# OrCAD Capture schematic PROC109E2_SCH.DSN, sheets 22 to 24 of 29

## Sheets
22 22. XDS110_DEBUGGER: size C; title: XDS110 DEBUGGER
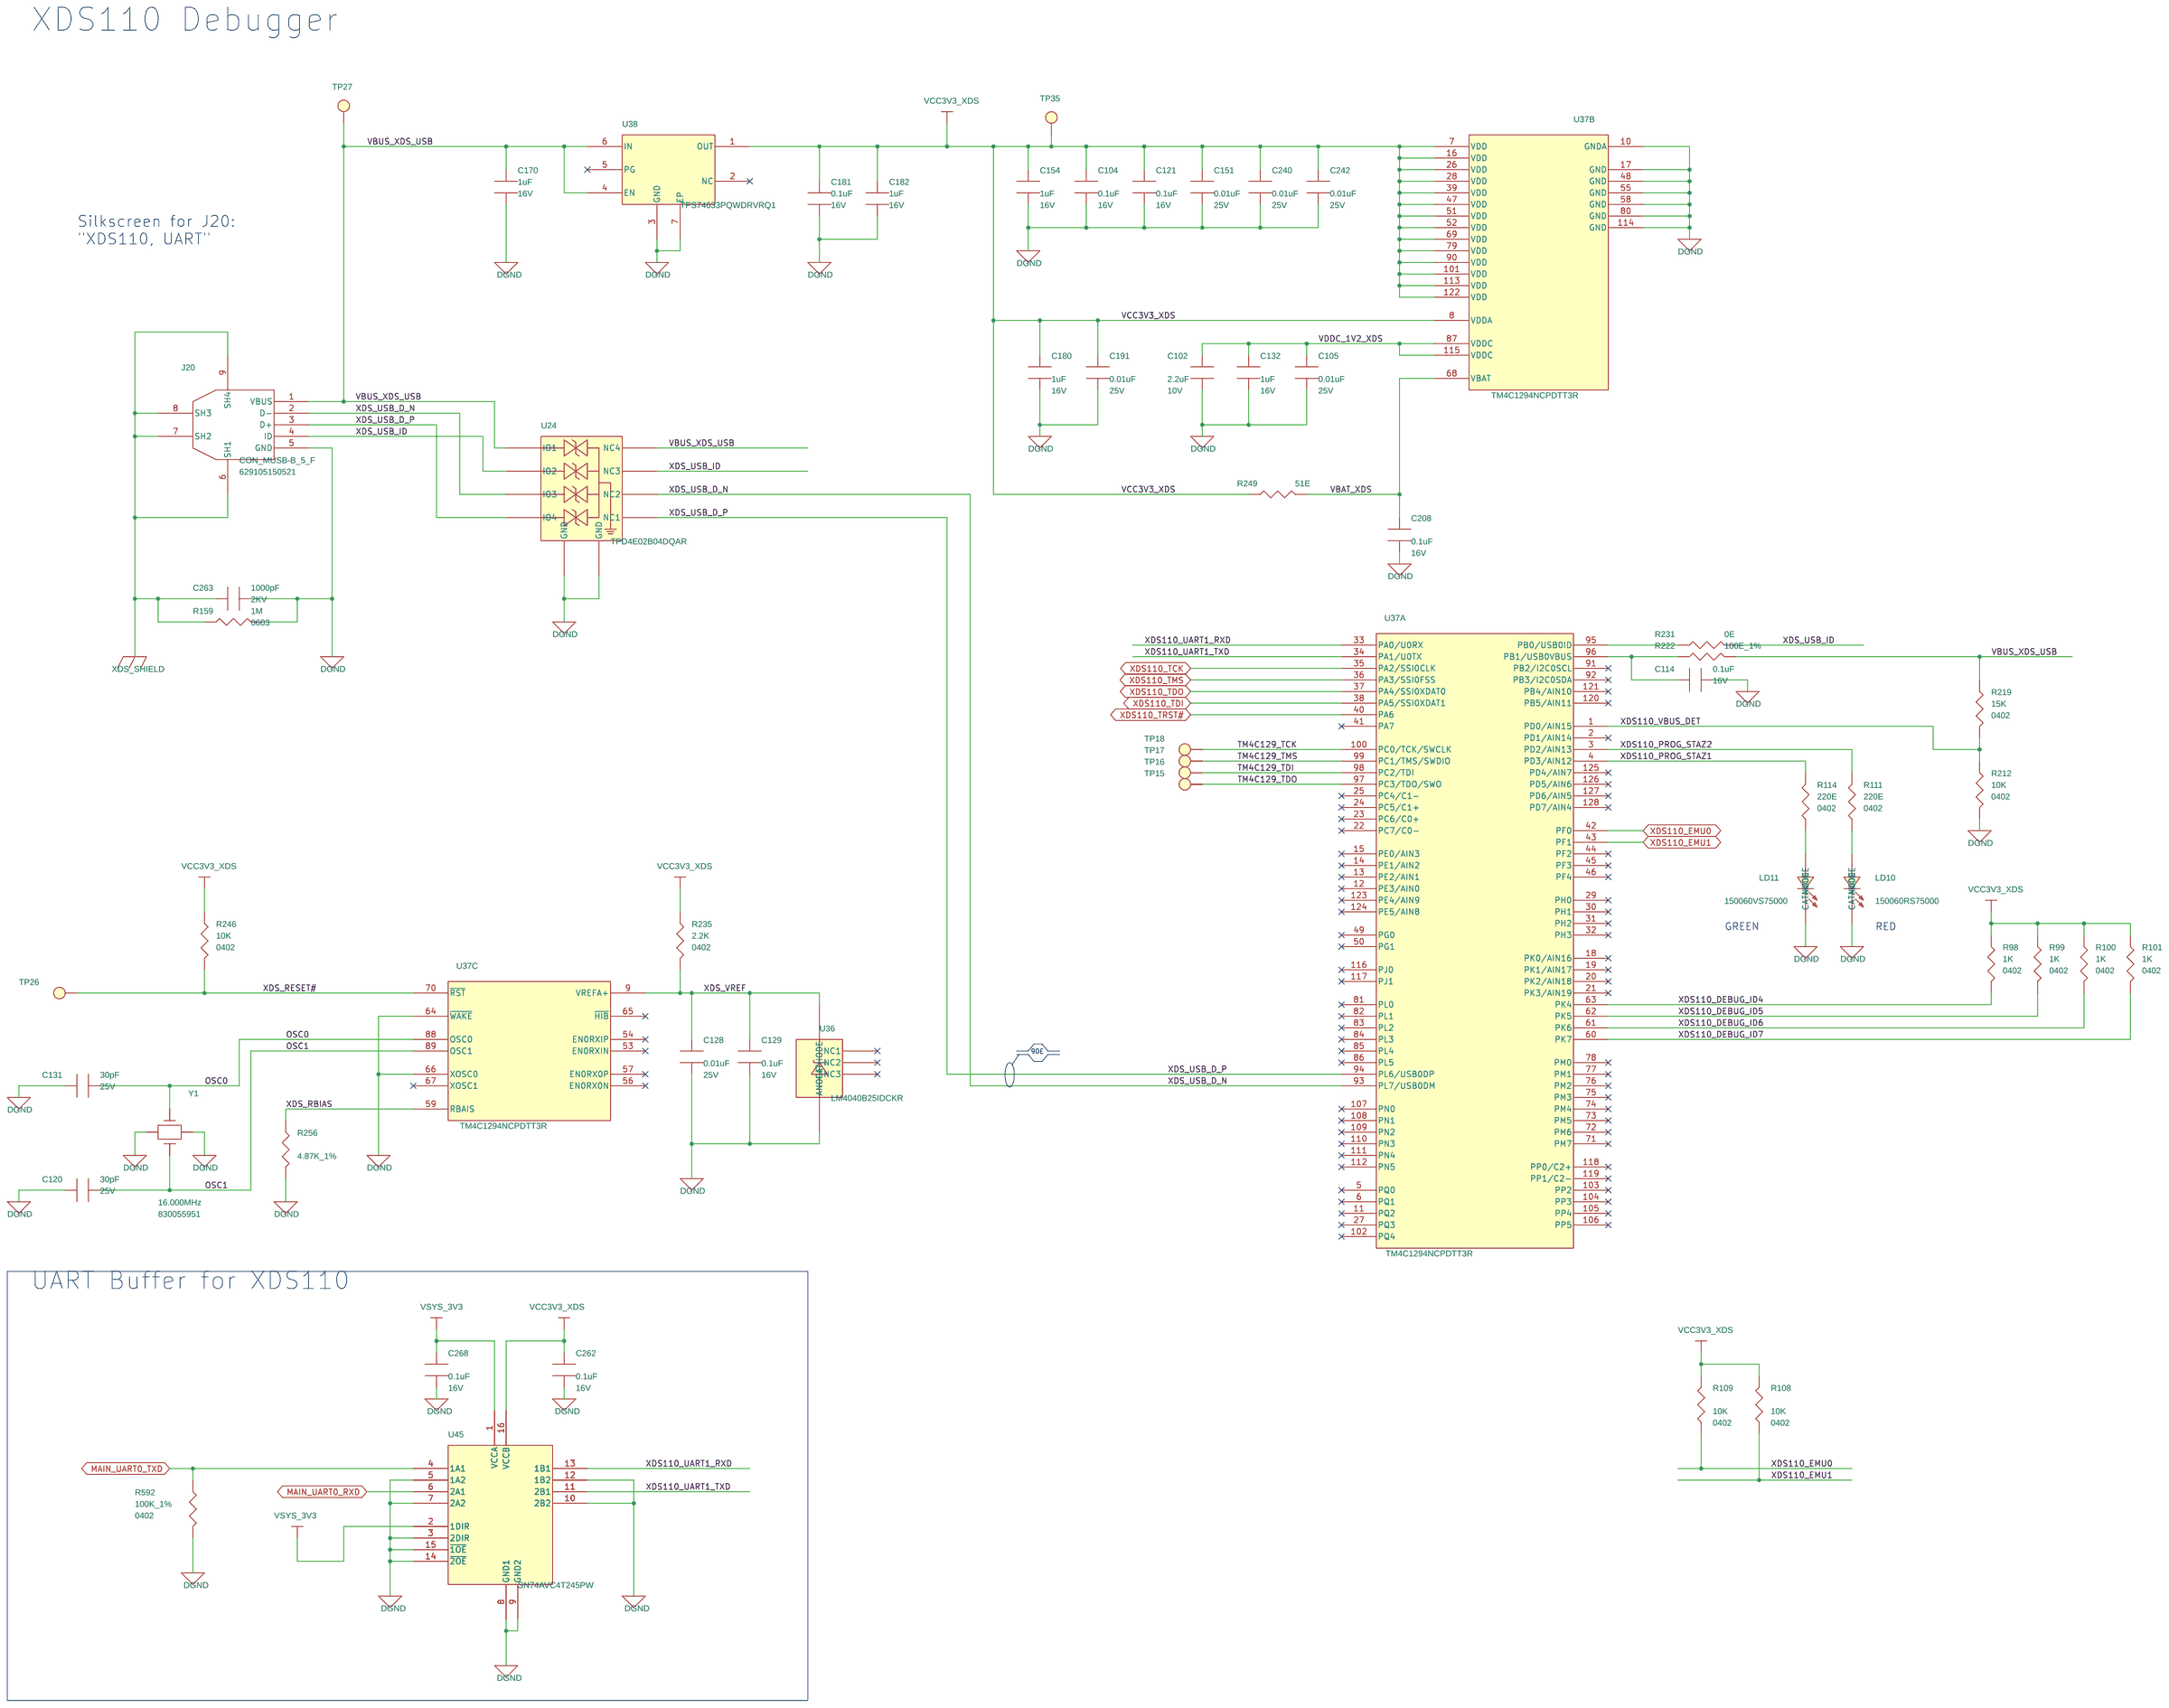
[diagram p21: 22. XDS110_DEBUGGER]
23 23. INDUSTRIAL_COMM_LEDs: size C; title: INDUSTRIAL COMMUNICATION LEDs
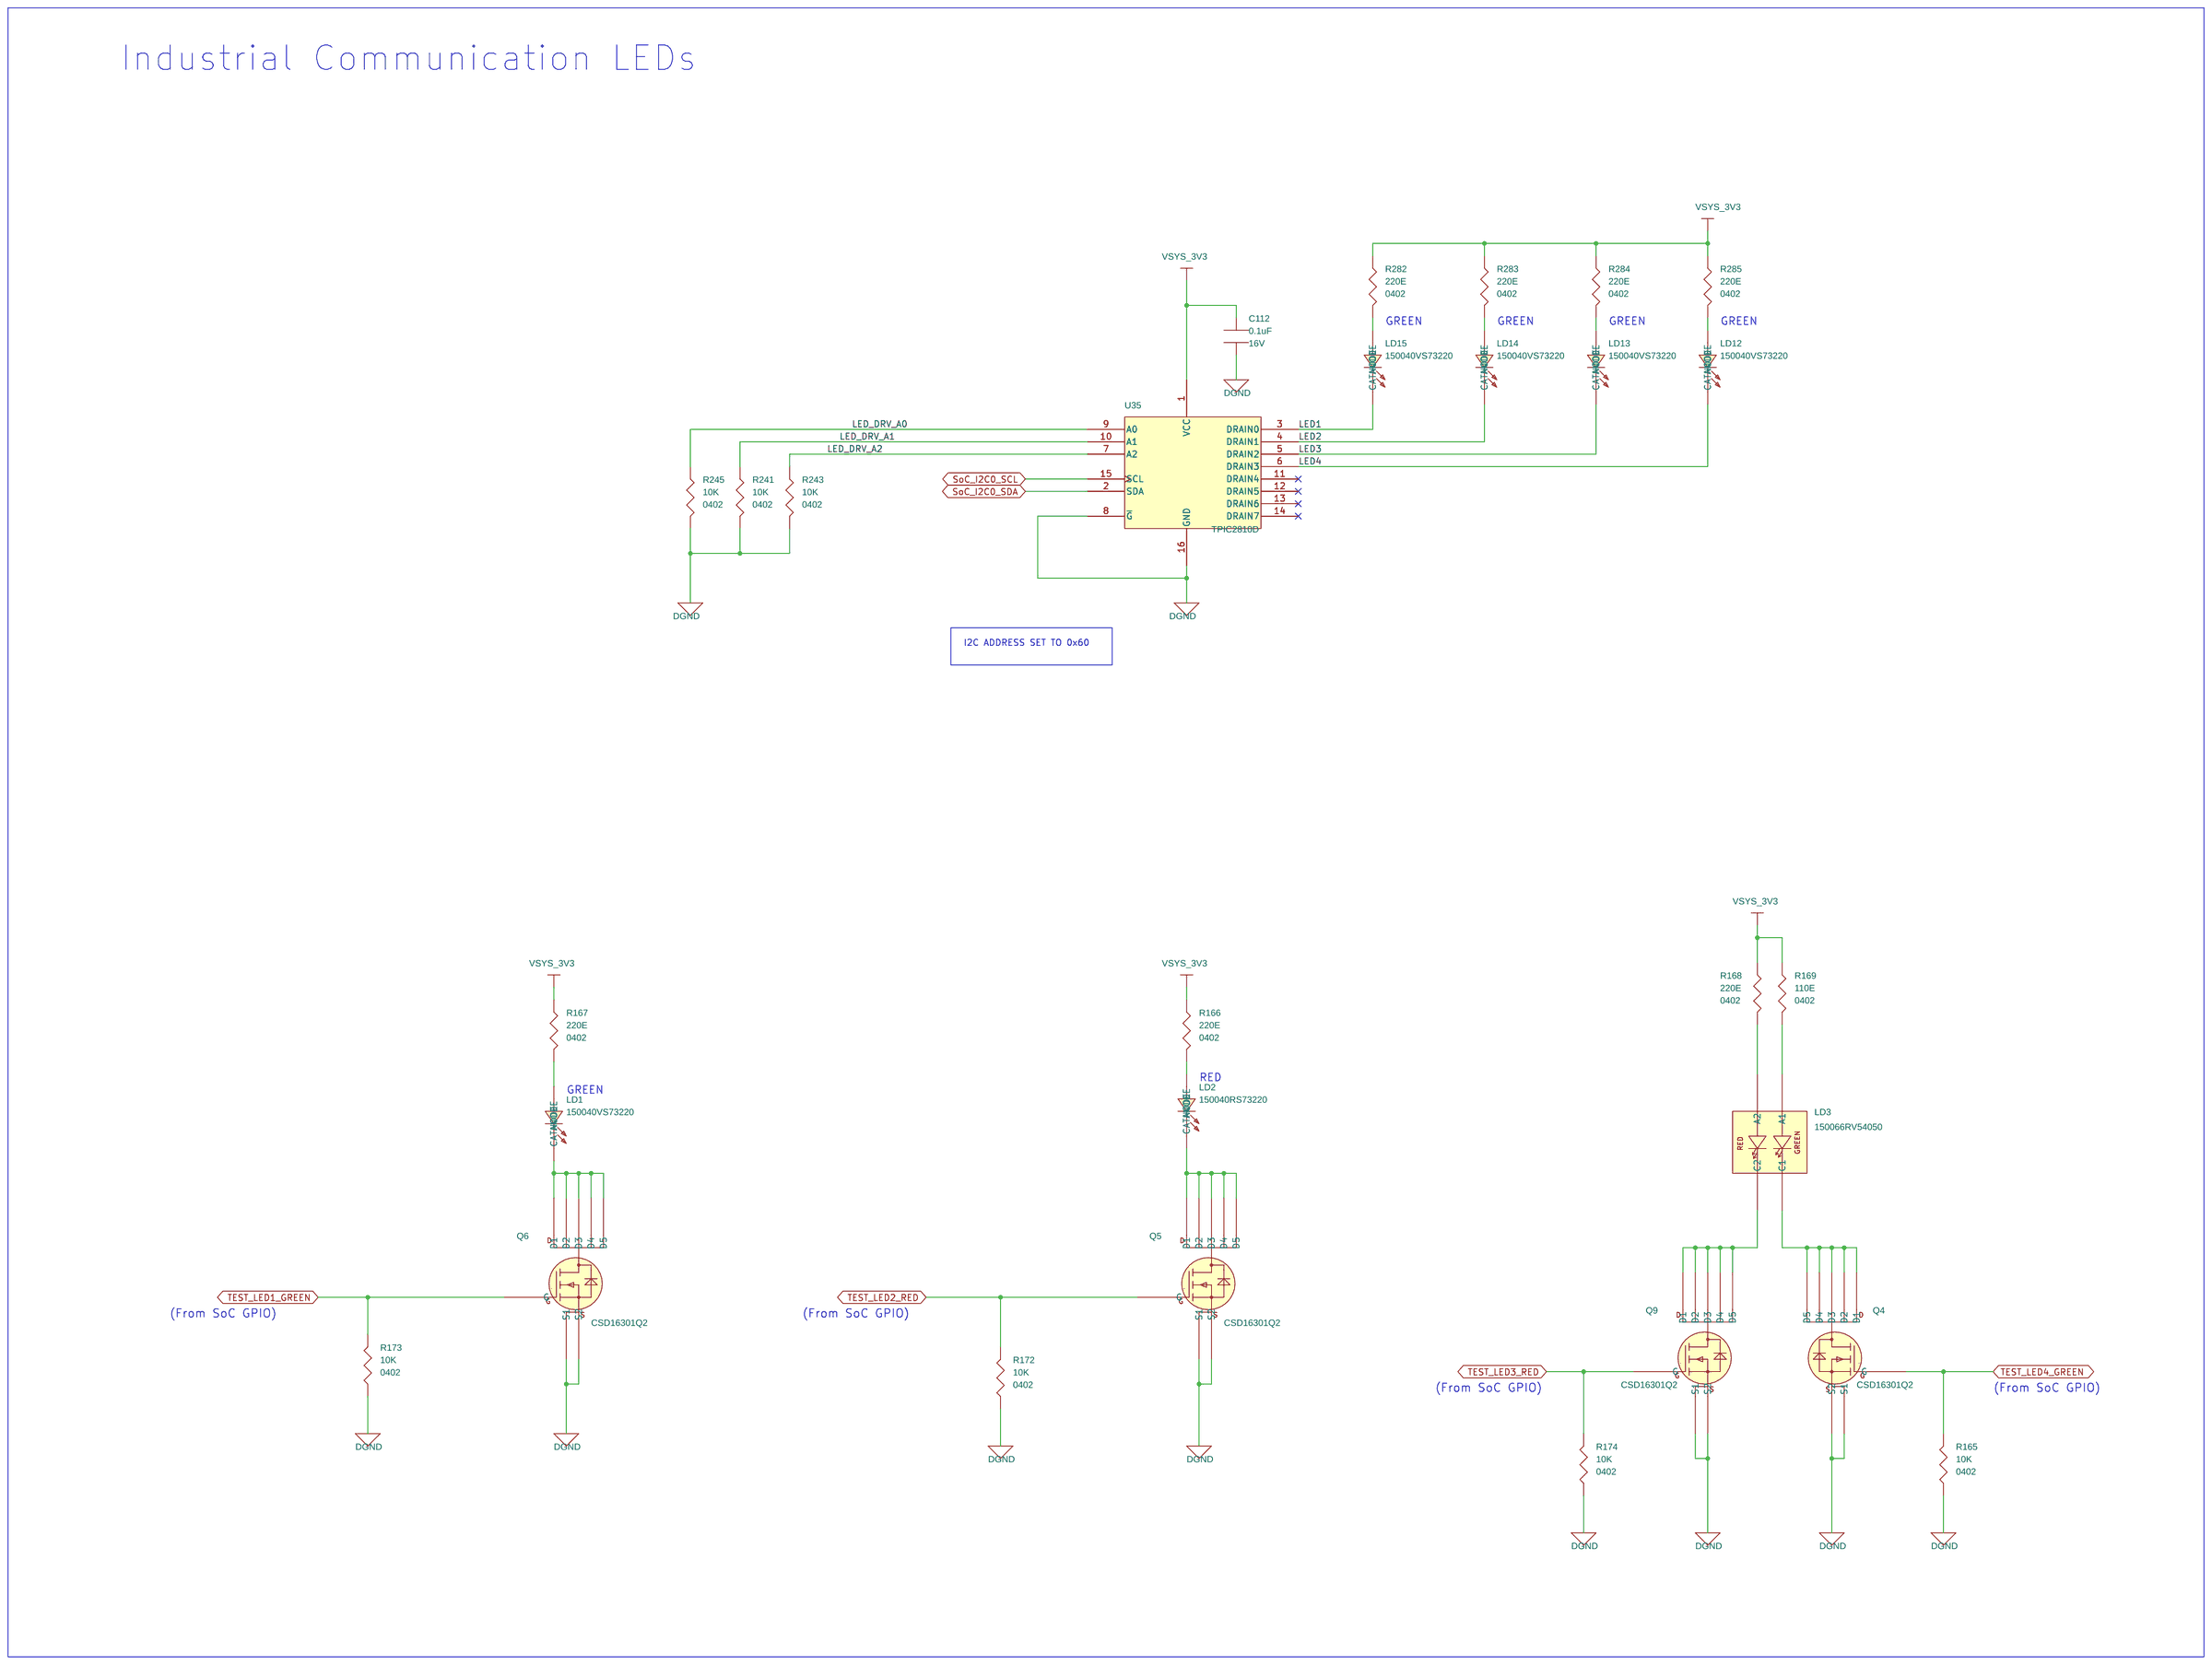
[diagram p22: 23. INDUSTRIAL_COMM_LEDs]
24 24. SOC_DIGITAL_POWER_DECAPs: size C; title: SoC Digital POWER & DECAPs
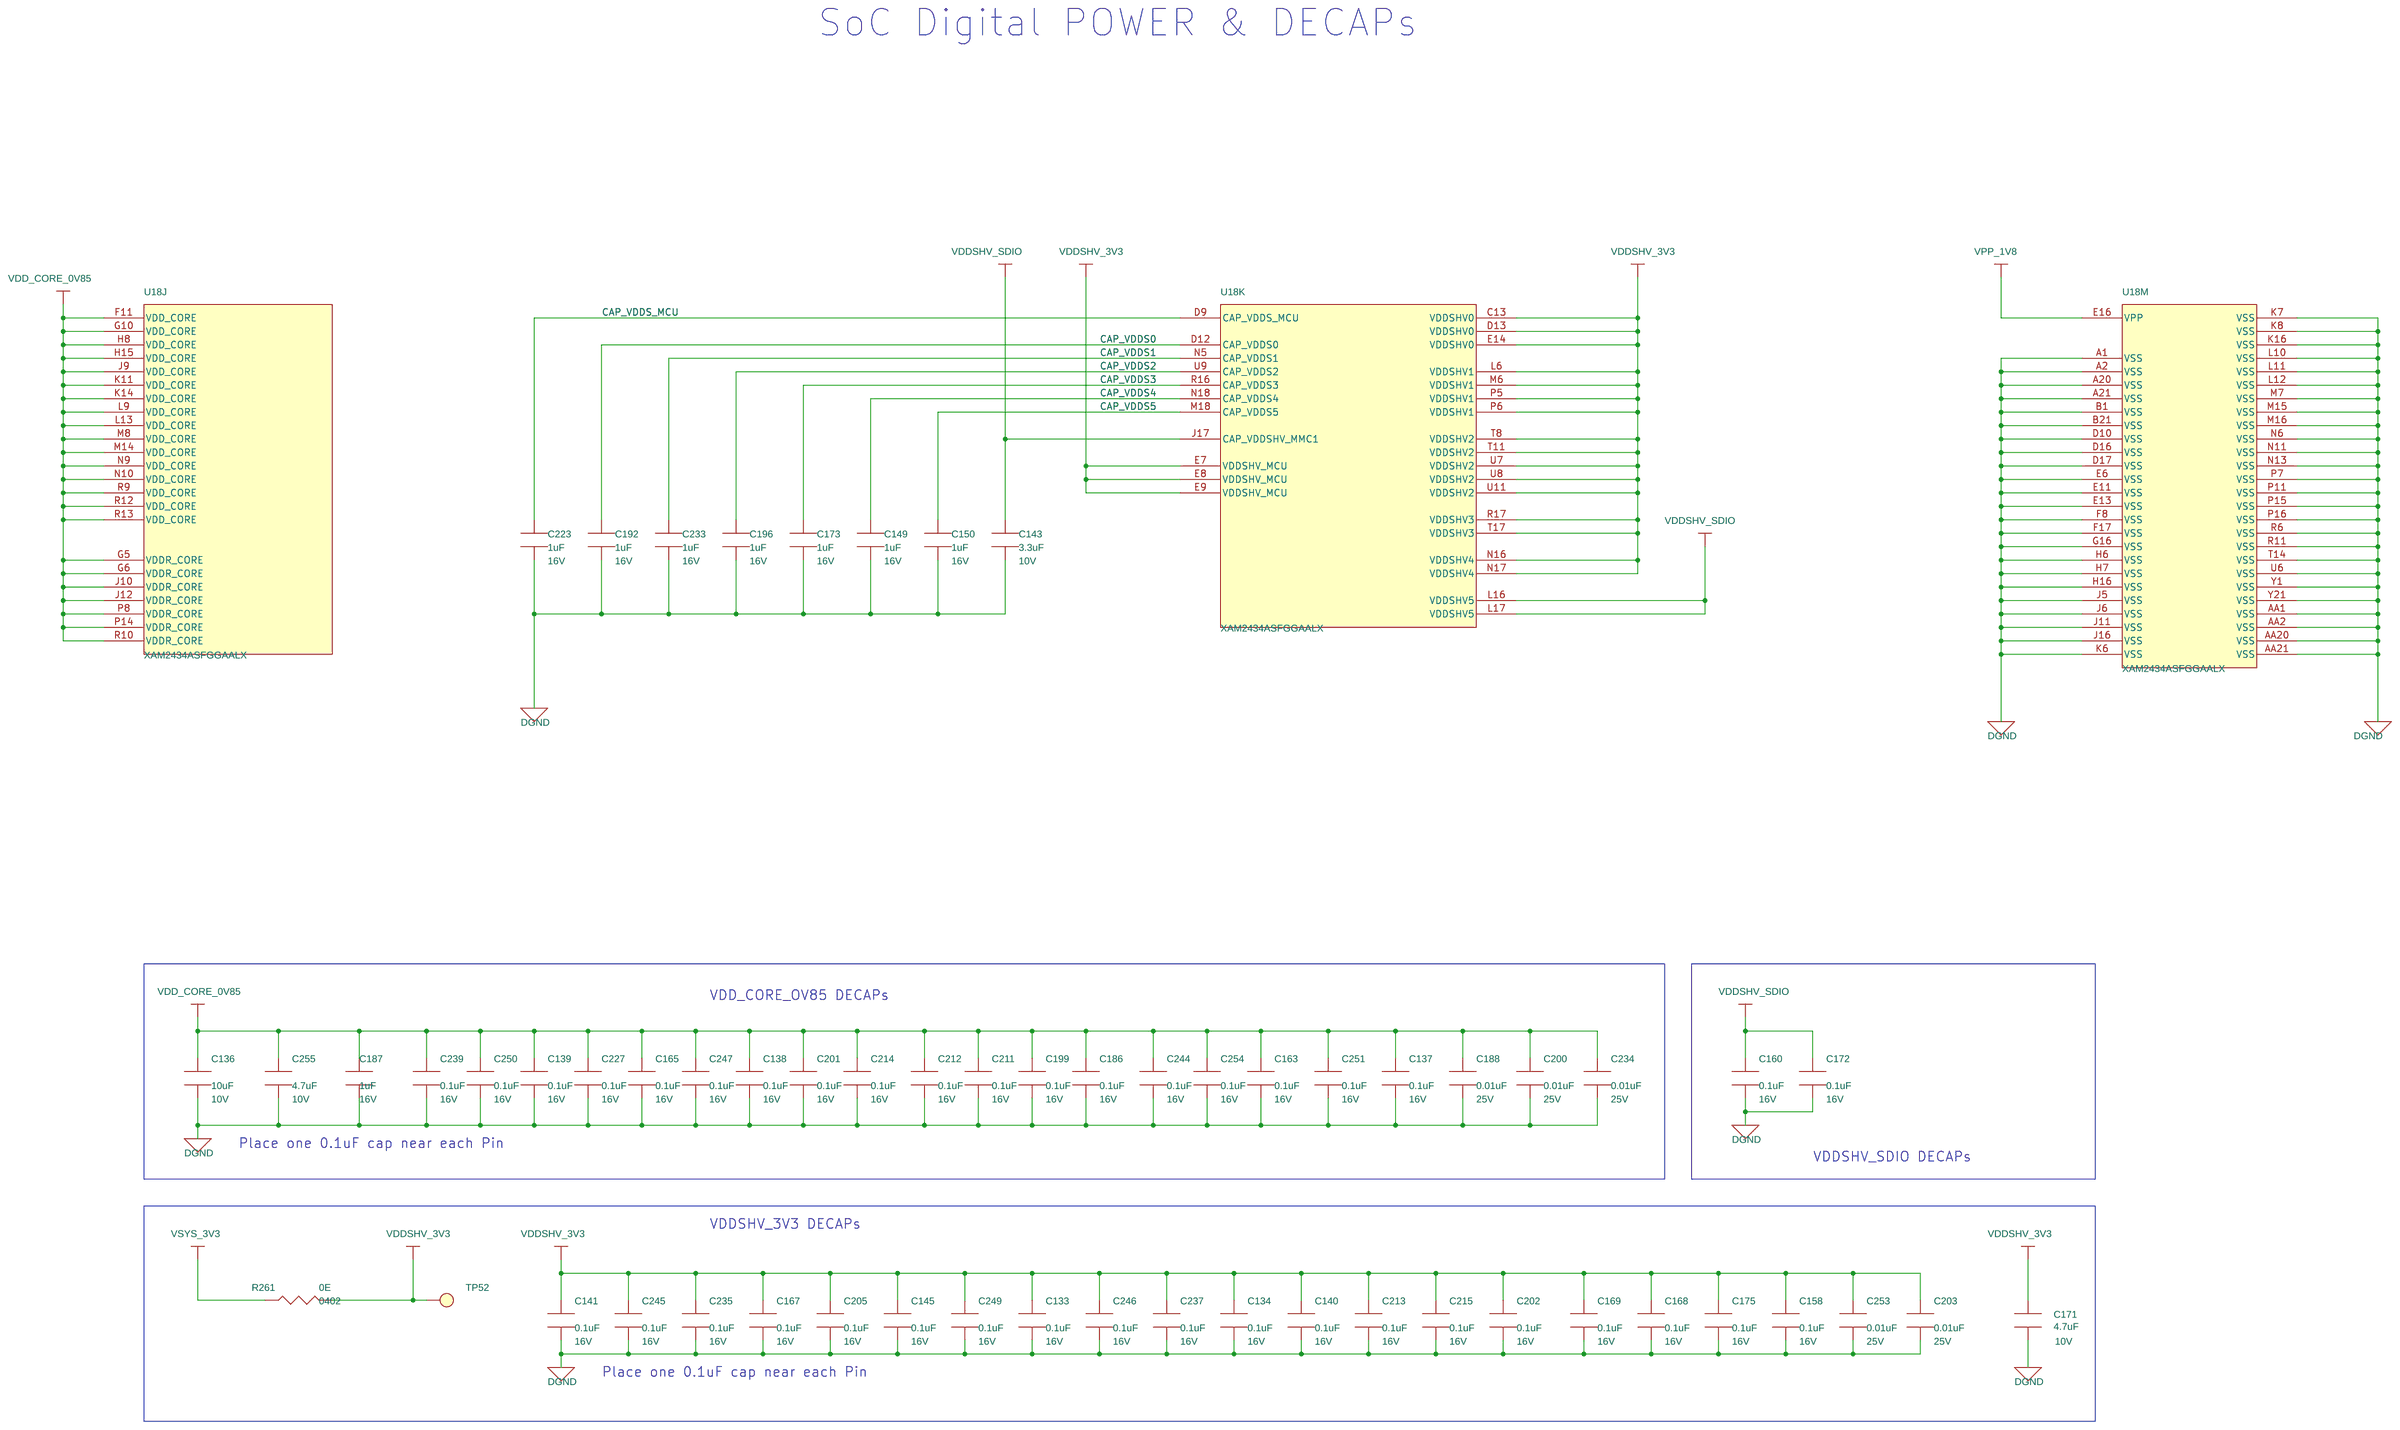
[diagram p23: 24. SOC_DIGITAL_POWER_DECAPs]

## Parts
sheet 15. SOC_QSPI_BOARD_ID_EEPROM
U18  XAM2434ASFGGAALX  [BGA293_19-68_440X440_1]  (sections A,B,C,D,E,F,G,H,I,J,K,L,M)
sheet 22. XDS110_DEBUGGER
C102  2.2uF  [CAP0402_0-75]
C104  0.1uF  [CAP0201_0-5]
C105  0.01uF  [CAP0201_0-5]
C114  0.1uF  [CAP0201_0-5]
C120  30pF  [CAP0201_0-5]
C121  0.1uF  [CAP0201_0-5]
C128  0.01uF  [CAP0201_0-5]
C129  0.1uF  [CAP0201_0-5]
C131  30pF  [CAP0201_0-5]
C132  1uF  [CAP0201_0-5]
C151  0.01uF  [CAP0201_0-5]
C154  1uF  [CAP0201_0-5]
C170  1uF  [CAP0201_0-5]
C180  1uF  [CAP0201_0-5]
C181  0.1uF  [CAP0201_0-5]
C182  1uF  [CAP0201_0-5]
C191  0.01uF  [CAP0201_0-5]
C208  0.1uF  [CAP0201_0-5]
C240  0.01uF  [CAP0201_0-5]
C242  0.01uF  [CAP0201_0-5]
C262  0.1uF  [CAP0201_0-5]
C263  1000pF  [CAP1210_1-5]
C268  0.1uF  [CAP0201_0-5]
J20  CON_MUSB-B_5_F  [CON_MUSBB5_629105150521_S_R_S_2-7]
LD10  150060RS75000  [LED_150060SS75000_70X40_SMD_0-8]
LD11  150060VS75000  [LED_150060SS75000_70X40_SMD_0-8]
R98  1K  [RES0402_0-5]
R99  1K  [RES0402_0-5]
R100  1K  [RES0402_0-5]
R101  1K  [RES0402_0-5]
R108  10K  [RES0402_0-5]
R109  10K  [RES0402_0-5]
R111  220E  [RES0402_0-5]
R114  220E  [RES0402_0-5]
R159  1M  [RES0603_0-75]
R212  10K  [RES0402_0-5]
R219  15K  [RES0402_0-5]
R222  100E_1%  [RES0402_0-5]
R231  0E  [RES0402_0-5]
R235  2.2K  [RES0402_0-5]
R246  10K  [RES0402_0-5]
R249  51E  [RES0402_0-5]
R256  4.87K_1%  [RES0402_0-5]
R592  100K_1%  [RES0402_0-5]
TP15  TP20_SMD  [TP20_SMD]
TP16  TP20_SMD  [TP20_SMD]
TP17  TP20_SMD  [TP20_SMD]
TP18  TP20_SMD  [TP20_SMD]
TP26  TP20_SMD  [TP20_SMD]
TP27  TP40_SMD  [TP40_SMD]
TP35  TP40_SMD  [TP40_SMD]
U24  TPD4E02B04DQAR  [USON10_TPD4E05U_40X100_0-6]
U36  LM4040B25IDCKR  [SC70-5_1-1]
U37  TM4C1294NCPDTT3R  [TQFP128_15-74_550X550_1-2]  (sections A,B,C)
U38  TPS74633PQWDRVRQ1  [SON6_25-59_85X85_0-8]
U45  SN74AVC4T245PW  [TSSOP16_25-59_205X180]
Y1  16.000MHz  [XTAL4_LFXTAL055474_130X110_SMD_0-8]
sheet 23. INDUSTRIAL_COMM_LEDs
C112  0.1uF  [CAP0201_0-5]
LD1  150040VS73220  [LED_150040GS73220_40X20_SMD_0-4]
LD2  150040RS73220  [LED_150040GS73220_40X20_SMD_0-4]
LD3  150066RV54050  [LED4_150066RV54050_70X60_SMD_0-7]
LD12  150040VS73220  [LED_150040GS73220_40X20_SMD_0-4]
LD13  150040VS73220  [LED_150040GS73220_40X20_SMD_0-4]
LD14  150040VS73220  [LED_150040GS73220_40X20_SMD_0-4]
LD15  150040VS73220  [LED_150040GS73220_40X20_SMD_0-4]
Q4  CSD16301Q2  [WSON6_CSD13202Q2_80X80_0-8]
Q5  CSD16301Q2  [WSON6_CSD13202Q2_80X80_0-8]
Q6  CSD16301Q2  [WSON6_CSD13202Q2_80X80_0-8]
Q9  CSD16301Q2  [WSON6_CSD13202Q2_80X80_0-8]
R165  10K  [RES0402_0-5]
R166  220E  [RES0402_0-5]
R167  220E  [RES0402_0-5]
R168  220E  [RES0402_0-5]
R169  110E  [RES0402_0-5]
R172  10K  [RES0402_0-5]
R173  10K  [RES0402_0-5]
R174  10K  [RES0402_0-5]
R241  10K  [RES0402_0-5]
R243  10K  [RES0402_0-5]
R245  10K  [RES0402_0-5]
R282  220E  [RES0402_0-5]
R283  220E  [RES0402_0-5]
R284  220E  [RES0402_0-5]
R285  220E  [RES0402_0-5]
U35  TPIC2810D  [SOIC16_1-8]
sheet 24. SOC_DIGITAL_POWER_DECAPs
C133  0.1uF  [CAP0201_0-5]
C134  0.1uF  [CAP0201_0-5]
C136  10uF  [CAP0402_0-75]
C137  0.1uF  [CAP0201_0-5]
C138  0.1uF  [CAP0201_0-5]
C139  0.1uF  [CAP0201_0-5]
C140  0.1uF  [CAP0201_0-5]
C141  0.1uF  [CAP0201_0-5]
C143  3.3uF  [CAP0603_1]
C145  0.1uF  [CAP0201_0-5]
C149  1uF  [CAP0201_0-5]
C150  1uF  [CAP0201_0-5]
C158  0.1uF  [CAP0201_0-5]
C160  0.1uF  [CAP0201_0-5]
C163  0.1uF  [CAP0201_0-5]
C165  0.1uF  [CAP0201_0-5]
C167  0.1uF  [CAP0201_0-5]
C168  0.1uF  [CAP0201_0-5]
C169  0.1uF  [CAP0201_0-5]
C171  4.7uF  [CAP0402_0-75]
C172  0.1uF  [CAP0201_0-5]
C173  1uF  [CAP0201_0-5]
C175  0.1uF  [CAP0201_0-5]
C186  0.1uF  [CAP0201_0-5]
C187  1uF  [CAP0201_0-5]
C188  0.01uF  [CAP0201_0-5]
C192  1uF  [CAP0201_0-5]
C196  1uF  [CAP0201_0-5]
C199  0.1uF  [CAP0201_0-5]
C200  0.01uF  [CAP0201_0-5]
C201  0.1uF  [CAP0201_0-5]
C202  0.1uF  [CAP0201_0-5]
C203  0.01uF  [CAP0201_0-5]
C205  0.1uF  [CAP0201_0-5]
C211  0.1uF  [CAP0201_0-5]
C212  0.1uF  [CAP0201_0-5]
C213  0.1uF  [CAP0201_0-5]
C214  0.1uF  [CAP0201_0-5]
C215  0.1uF  [CAP0201_0-5]
C223  1uF  [CAP0201_0-5]
C227  0.1uF  [CAP0201_0-5]
C233  1uF  [CAP0201_0-5]
C234  0.01uF  [CAP0201_0-5]
C235  0.1uF  [CAP0201_0-5]
C237  0.1uF  [CAP0201_0-5]
C239  0.1uF  [CAP0201_0-5]
C244  0.1uF  [CAP0201_0-5]
C245  0.1uF  [CAP0201_0-5]
C246  0.1uF  [CAP0201_0-5]
C247  0.1uF  [CAP0201_0-5]
C249  0.1uF  [CAP0201_0-5]
C250  0.1uF  [CAP0201_0-5]
C251  0.1uF  [CAP0201_0-5]
C253  0.01uF  [CAP0201_0-5]
C254  0.1uF  [CAP0201_0-5]
C255  4.7uF  [CAP0402_0-75]
R261  0E  [RES0402_0-5]
TP52  TP20_SMD  [TP20_SMD]

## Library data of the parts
U18 = AM243X_SOC_LP_EVM_BGA293: IC AM243x SoC_LP_EVM MICROPROCESSOR BGA293; Chkd/date: MANIRAJA/131120; Crtd /date: ALVY/121120; Custom_Duty: 15%; Customs_HS_Code: 85423100; Distributor_name: NA; Distributor_part_number: NA; Footprint Path: Y:\MIS_DATABASE\Library\ALTIUM_TOOL\PCB_FOOTPRINTS\Altium_Footprint_Lib.PcbLib; Height: 1.00MM; Library Path: Y:\MIS_DATABASE\Library\ALTIUM_TOOL\SCHEMATICS_PARTS\MS_MICROPROCESSOR_Library.schlib; Library Ref: AM243x SoC_LP_EVM_BGA293; Mfr_name: TEXAS INSTRUMENTS; Mistral Part No: 141220110003; Package: BGA293; Part_type: ICS\DIGITAL\MICROPROCESSOR; Project: TI_AM243x LP EVM; RoHS: NA; Temperature: NA; Tolerance: NA; Voltage: NA; Wattage: NA; Weight: NA; Datasheet: Y:\MIS_DATABASE\DATASHEETS\ICS\DIGITAL\MICROCONTROLLER\AM243x SoC-FP.PDF
C102 = CAP: CAP CERAMIC 2.2uF 10V 20% X5R 0402; Chkd/date: MANIRAJA/170820; Crtd /date: ALVY/170820; Custom_Duty: 15%; Customs_HS_Code: 85322990; Distributor_name: DIGIKEY; Distributor_part_number: 732-7490-1-ND; Footprint Path: Y:\MIS_DATABASE\Library\ALTIUM_TOOL\PCB_FOOTPRINTS\Altium_Footprint_Lib.PcbLib; Height: 0.55MM; Library Path: Y:\MIS_DATABASE\Library\ALTIUM_TOOL\SCHEMATICS_PARTS\MS_DISCRETE_Library.schlib; Mfr_name: WURTH ELECTRONICS; Mfr_part_number: 885012105013; Mistral Part No: 120019040036-R; Package: 0402; Part_type: CAPACITORS\CERAMIC; Project: AM64x_EVM_BRD; RoHS: RoHS; Temperature: -55°C+85°C; Tolerance: 20%; Voltage: 10V; Wattage: NA; Weight: 0.65mg; Datasheet: Y:\MIS_DATABASE\DATASHEETS\CAPACITORS\885012105013.PDF
C104 C114 C121 C129 C133 C134 C137-C141 C145 C158 C160 C163 C165 C167-C169 C172 C175 C181 C186 C199 C201 C202 C205 C208 C211-C215 C227 C235 C237 C239 C244-C247 C249-C251 C254 C262 C268 = CAP: CAP CERAMIC 0.1uF 16V 10% X5R 0201; Chkd/date: MANIRAJA/230118; Crtd /date: MANIRAJA/230118; Custom_Duty: 15%; Customs_HS_Code: 85322990; Distributor_name: DIGIKEY; Distributor_part_number: 490-14305-1-ND; Footprint Path: Y:\MIS_DATABASE\Library\ALTIUM_TOOL\PCB_FOOTPRINTS\Altium_Footprint_Lib.PcbLib; Height: 0.33MM; Library Path: Y:\MIS_DATABASE\Library\ALTIUM_TOOL\SCHEMATICS_PARTS\MS_DISCRETE_Library.schlib; Mfr_name: MURATA; Mfr_part_number: GRM033R61C104KE14D; Mistral Part No: 120009030072-R; Package: 0201; Part_type: CAPACITORS\CERAMIC; Project: TI_MAXIE_CPB; RoHS: RoHS; Temperature: -55°C+85°C; Tolerance: 10%; Voltage: 16V; Wattage: NA; Weight: 0.33mg; Datasheet: Y:\MIS_DATABASE\DATASHEETS\CAPACITORS\GRM033R61C104KE14.PDF
C105 C128 C151 C188 C191 C200 C203 C234 C240 C242 C253 = CAP: CAP CERAMIC 0.01uF 25V 10% X7R 0201; Chkd/date: MANIRAJA/080519; Crtd /date: ALVY/080519; Custom_Duty: 15%; Customs_HS_Code: 85322990; Distributor_name: DIGIKEY; Distributor_part_number: 490-14454-1-ND; Footprint Path: Y:\MIS_DATABASE\Library\ALTIUM_TOOL\PCB_FOOTPRINTS\Altium_Footprint_Lib.PcbLib; Height: 0.33MM; Library Path: Y:\MIS_DATABASE\Library\ALTIUM_TOOL\SCHEMATICS_PARTS\MS_DISCRETE_Library.schlib; Mfr_name: MURATA; Mfr_part_number: GRM033R71E103KE14D; Mistral Part No: 120019050002-R; Package: 0201; Part_type: CAPACITORS\CERAMIC; Project: BRUKER_SD820_COMMONDO; RoHS: RoHS; Temperature: -55°C+125°C; Tolerance: 10%; Voltage: 25V; Wattage: NA; Weight: 0.33mg; Datasheet: Y:\MIS_DATABASE\DATASHEETS\CAPACITORS\GRM033R71E103KE14.PDF
C120 C131 = CAP: CAP CERAMIC 30pF 25V 5% C0G(NP0) 0201; Chkd/date: ALVY/050221; Crtd /date: MANIRAJA/050221; Custom_Duty: 15%; Customs_HS_Code: 85322990; Distributor_name: DIGIKEY; Distributor_part_number: 490-12677-1-ND; Footprint Path: Y:\MIS_DATABASE\Library\ALTIUM_TOOL\PCB_FOOTPRINTS\Altium_Footprint_Lib.PcbLib; Height: 0.33MM; Library Path: Y:\MIS_DATABASE\Library\ALTIUM_TOOL\SCHEMATICS_PARTS\MS_DISCRETE_Library.schlib; Mfr_name: MURATA; Mfr_part_number: GRM0335C1E300JA01D; Mistral Part No: 120009030363-R; Package: 0201; Part_type: CAPACITORS\CERAMIC; Project: TI_AM243x LP EVM; RoHS: RoHS; Temperature: -55°C+125°C; Tolerance: 5%; Voltage: 25V; Wattage: NA; Weight: 0.33mg; Datasheet: Y:\MIS_DATABASE\DATASHEETS\CAPACITORS\GRM0335C1E300JA01.PDF
C132 C149 C150 C154 C170 C173 C180 C182 C187 C192 C196 C223 C233 = CAP: CAP CERAMIC 1uF 16V 20% X5R 0201; Chkd/date: MANIRAJA/300520; Crtd /date: ALVY/260520; Custom_Duty: 15%; Customs_HS_Code: 85322990; Distributor_name: DIGIKEY; Distributor_part_number: 490-18654-1-ND; Footprint Path: Y:\MIS_DATABASE\Library\ALTIUM_TOOL\PCB_FOOTPRINTS\Altium_Footprint_Lib.PcbLib; Height: 0.39MM; Library Path: Y:\MIS_DATABASE\Library\ALTIUM_TOOL\SCHEMATICS_PARTS\MS_DISCRETE_Library.schlib; Mfr_name: MURATA; Mfr_part_number: GRM033R61C105ME15D; Mistral Part No: 120018090038-R; Package: 0201; Part_type: CAPACITORS\CERAMIC; Project: QCS610_NANOSOM; RoHS: RoHS; Temperature: -55°C+85°C; Tolerance: 20%; Voltage: 16V; Wattage: NA; Weight: 0.33mg; Datasheet: Y:\MIS_DATABASE\DATASHEETS\CAPACITORS\GRM033R61C105ME15.PDF
C263 = CAP: CAP CERAMIC 1000pF 2KV 10% X7R 1210; Chkd/date: ALVY/071220; Crtd /date: MANIRAJA/071220; Custom_Duty: 15%; Customs_HS_Code: 85322990; Distributor_name: DIGIKEY; Distributor_part_number: 732-12130-1-ND; Footprint Path: Y:\MIS_DATABASE\Library\ALTIUM_TOOL\PCB_FOOTPRINTS\Altium_Footprint_Lib.PcbLib; Height: 1.35MM; Library Path: Y:\MIS_DATABASE\Library\ALTIUM_TOOL\SCHEMATICS_PARTS\MS_DISCRETE_Library.schlib; Mfr_name: WURTH ELEKTRONIK; Mfr_part_number: 885342209009; Mistral Part No: 120020120008-R; Package: 1210; Part_type: CAPACITORS\CERAMIC; Project: TI_AM243x LP EVM; RoHS: RoHS; Temperature: -55°C+125°C; Tolerance: 10%; Voltage: 2KV; Wattage: NA; Weight: 19.234mg; Datasheet: Y:\MIS_DATABASE\DATASHEETS\CAPACITORS\885342209009.PDF
J20 = CON_USB_MINI-B: CON MICRO USB TYPE B 5POS FEMALE RT SMD; Chkd/date: MANIRAJA/150519; Crtd /date: ALVY/150519; Custom_Duty: 24%; Customs_HS_Code: 85369090; Distributor_name: DIGIKEY; Distributor_part_number: 732-5960-1-ND; Footprint Path: Y:\MIS_DATABASE\Library\ALTIUM_TOOL\PCB_FOOTPRINTS\Altium_Footprint_Lib.PcbLib; Height: 2.66MM; Library Path: Y:\MIS_DATABASE\Library\ALTIUM_TOOL\SCHEMATICS_PARTS\MS_CONNECTOR_Library.schlib; Mfr_name: WURTH ELECTRONICS; Mfr_part_number: 629105150521; Mistral Part No: 150019050015-R; Package: SMD; Part_type: CONNECTOR\USB; Project: NEXTNAV_ALT-STATION_ATE_BRD; RoHS: RoHS; Temperature: -40°C+85°C; Tolerance: NA; Voltage: NA; Wattage: NA; Weight: 360mg; Datasheet: Y:\MIS_DATABASE\DATASHEETS\CONNECTORS\629105150521.PDF
LD10 = DIODE_LED: DIODE LED RED SMD; Chkd/date: MANIRAJA/131120; Crtd /date: ALVY/121120; Custom_Duty: 24%; Customs_HS_Code: 85439000; Distributor_name: DIGIKEY; Distributor_part_number: 732-4978-1-ND; Footprint Path: Y:\MIS_DATABASE\Library\ALTIUM_TOOL\PCB_FOOTPRINTS\Altium_Footprint_Lib.PcbLib; Height: 0.80MM; Library Path: Y:\MIS_DATABASE\Library\ALTIUM_TOOL\SCHEMATICS_PARTS\MS_OPTO_Library.schlib; Mfr_name: WURTH ELECTRONICS; Mistral Part No: 130020110037-R; Package: SMD; Part_type: OPTO\LED; Project: TI_AM243x LP EVM; RoHS: RoHS; Temperature: -40°C+85°C; Tolerance: NA; Voltage: NA; Wattage: NA; Weight: 23mg; Datasheet: Y:\MIS_DATABASE\DATASHEETS\DISCRETES\LEDS\150060RS75000.PDF
LD11 = DIODE_LED: DIODE LED BRIGHT GREEN SMD; Chkd/date: MANIRAJA/220720; Crtd /date: ALVY/210720; Custom_Duty: 24%; Customs_HS_Code: 85439000; Distributor_name: DIGIKEY; Distributor_part_number: 732-4980-1-ND; Footprint Path: Y:\MIS_DATABASE\Library\ALTIUM_TOOL\PCB_FOOTPRINTS\Altium_Footprint_Lib.PcbLib; Height: 0.80MM; Library Path: Y:\MIS_DATABASE\Library\ALTIUM_TOOL\SCHEMATICS_PARTS\MS_OPTO_Library.schlib; Mfr_name: WURTH ELECTRONICS; Mistral Part No: 130020070019-R; Package: SMD; Part_type: OPTO\LED; Project: AM64x-IO LINK BRD; RoHS: RoHS; Temperature: -40°C+85°C; Tolerance: NA; Voltage: NA; Wattage: NA; Weight: 25mg; Datasheet: Y:\MIS_DATABASE\DATASHEETS\DISCRETES\LEDS\150060VS75000.PDF
R98-R101 = RESISTOR: RES 1K 1/16W 5% 0402; Chkd/date: VASANTHA/120516; Crtd /date: VASANTHA/120516; Custom_Duty: 15%; Customs_HS_Code: 85332119; Distributor_name: DIGIKEY; Distributor_part_number: 311-1.0KJRCT-ND; Footprint Path: Y:\MIS_DATABASE\Library\ALTIUM_TOOL\PCB_FOOTPRINTS\Altium_Footprint_Lib.PcbLib; Height: 0.40MM; Library Path: Y:\MIS_DATABASE\Library\ALTIUM_TOOL\SCHEMATICS_PARTS\MS_DISCRETE_Library.schlib; Mfr_name: YAGEO AMERICA; Mfr_part_number: RC0402JR-071KL; Mistral Part No: 110010070006-R; Package: 0402; Part_type: RESISTORS\FIXED; Project: TMDXCSK368; RoHS: RoHS; Temperature: -55°C+155°C; Tolerance: 5%; Voltage: NA; Wattage: 1/16W; Weight: 0.65mg; Datasheet: Y:\MIS_DATABASE\DATASHEETS\RESISTORS\RCXXXXL-SER_MAR18.PDF
R108 R109 R165 R172-R174 R212 R241 R243 R245 R246 = RESISTOR: RES 10K 1/16W 5% 0402; Chkd/date: VASANTHA/061216; Crtd /date: MAZHAR/230805; Custom_Duty: 15%; Customs_HS_Code: 85332119; Distributor_name: DIGIKEY; Distributor_part_number: 311-10KJRCT-ND; Footprint Path: Y:\MIS_DATABASE\Library\ALTIUM_TOOL\PCB_FOOTPRINTS\Altium_Footprint_Lib.PcbLib; Height: 0.40MM; Library Path: Y:\MIS_DATABASE\Library\ALTIUM_TOOL\SCHEMATICS_PARTS\MS_DISCRETE_Library.schlib; Mfr_name: YAGEO AMERICA; Mfr_part_number: RC0402JR-0710KL; Mistral Part No: 110011060021-R; Package: 0402; Part_type: RESISTORS\FIXED; Project: HSE; RoHS: RoHS; Temperature: -55°C+155°C; Tolerance: 5%; Voltage: NA; Wattage: 1/16W; Weight: 0.65mg; Datasheet: Y:\MIS_DATABASE\DATASHEETS\RESISTORS\RCXXXXL-SER_MAR18.PDF
R111 R114 R166-R168 R282-R285 = RESISTOR: RES 220E 1/16W 5% 0402; Chkd/date: ALVY/091220; Crtd /date: MANIRAJA/091220; Custom_Duty: 15%; Customs_HS_Code: 85332119; Distributor_name: DIGIKEY; Distributor_part_number: 311-220JRCT-ND; Footprint Path: Y:\MIS_DATABASE\Library\ALTIUM_TOOL\PCB_FOOTPRINTS\Altium_Footprint_Lib.PcbLib; Height: 0.40MM; Library Path: Y:\MIS_DATABASE\Library\ALTIUM_TOOL\SCHEMATICS_PARTS\MS_DISCRETE_Library.schlib; Mfr_name: YAGEO AMERICA; Mfr_part_number: RC0402JR-07220RL; Mistral Part No: 110020120013-R; Package: 0402; Part_type: RESISTORS\FIXED; Project: TI_AM243x LP EVM; RoHS: RoHS; Temperature: -55°C+155°C; Tolerance: 5%; Voltage: NA; Wattage: 1/16W; Weight: 0.65mg; Datasheet: Y:\MIS_DATABASE\DATASHEETS\RESISTORS\RCXXXXL-SER_MAR18.PDF
R159 = RESISTOR: RES 1M 1/10W 5% 0603; Chkd/date: ALVY/091220; Crtd /date: MANIRAJA/091220; Custom_Duty: 15%; Customs_HS_Code: 85332119; Distributor_name: DIGIKEY; Distributor_part_number: 311-1.0MGRCT-ND; Footprint Path: Y:\MIS_DATABASE\Library\ALTIUM_TOOL\PCB_FOOTPRINTS\Altium_Footprint_Lib.PcbLib; Height: 0.55MM; Library Path: Y:\MIS_DATABASE\Library\ALTIUM_TOOL\SCHEMATICS_PARTS\MS_DISCRETE_Library.schlib; Mfr_name: YAGEO AMERICA; Mfr_part_number: RC0603JR-071ML; Mistral Part No: 110009030413-R; Package: 0603; Part_type: RESISTORS\FIXED; Project: TI_AM243x LP EVM; RoHS: RoHS; Temperature: -55°C+155°C; Tolerance: 5%; Voltage: NA; Wattage: 1/10W; Weight: 2mg; Datasheet: Y:\MIS_DATABASE\DATASHEETS\RESISTORS\RCXXXXL-SER_MAR18.PDF
R219 = RESISTOR: RES 15K 1/10W 5% 0402; Chkd/date: VASANTHA/061216; Crtd /date: GEETHA/260406; Custom_Duty: 15%; Customs_HS_Code: 85332119; Distributor_name: DIGIKEY; Distributor_part_number: P15KJCT-ND; Footprint Path: Y:\MIS_DATABASE\Library\ALTIUM_TOOL\PCB_FOOTPRINTS\Altium_Footprint_Lib.PcbLib; Height: 0.40MM; Library Path: Y:\MIS_DATABASE\Library\ALTIUM_TOOL\SCHEMATICS_PARTS\MS_DISCRETE_Library.schlib; Mfr_name: PANASONIC-ECG; Mfr_part_number: ERJ-2GEJ153X; Mistral Part No: 110009030341-R; Package: 0402; Part_type: RESISTORS\FIXED; Project: RED EYE; RoHS: RoHS; Temperature: -55°C+155°C; Tolerance: 5%; Voltage: NA; Wattage: 1/10W; Weight: 0.8mg; Datasheet: Y:\MIS_DATABASE\DATASHEETS\RESISTORS\PAN-ERJSER_NOV17.PDF
R222 = RESISTOR: RES 100E 1/10W 1% 0402; Chkd/date: MANIRAJA/130617; Crtd /date: JEBRAN/040715; Custom_Duty: 15%; Customs_HS_Code: 85332119; Distributor_name: DIGIKEY; Distributor_part_number: P100LCT-ND; Footprint Path: Y:\MIS_DATABASE\Library\ALTIUM_TOOL\PCB_FOOTPRINTS\Altium_Footprint_Lib.PcbLib; Height: 0.40MM; Library Path: Y:\MIS_DATABASE\Library\ALTIUM_TOOL\SCHEMATICS_PARTS\MS_DISCRETE_Library.schlib; Mfr_name: PANASONIC-ECG; Mfr_part_number: ERJ-2RKF1000X; Mistral Part No: 110018020036-R; Package: 0402; Part_type: RESISTORS\FIXED; Project: CYPHY_FVB; RoHS: RoHS; Temperature: -55°C+155°C; Tolerance: 1%; Voltage: NA; Wattage: 1/10W; Weight: 0.8mg; Datasheet: Y:\MIS_DATABASE\DATASHEETS\RESISTORS\PAN-ERJSER_NOV17.PDF
R231 R261 = RESISTOR: RES 0E 1/16W 5% 0402; Chkd/date: VASANTHA/291216; Crtd /date: CHAITHANYA/300911; Custom_Duty: 15%; Customs_HS_Code: 85332119; Distributor_name: DIGIKEY; Distributor_part_number: 311-0.0JRCT-ND; Footprint Path: Y:\MIS_DATABASE\Library\ALTIUM_TOOL\PCB_FOOTPRINTS\Altium_Footprint_Lib.PcbLib; Height: 0.40MM; Library Path: Y:\MIS_DATABASE\Library\ALTIUM_TOOL\SCHEMATICS_PARTS\MS_DISCRETE_Library.schlib; Mfr_name: YAGEO AMERICA; Mfr_part_number: RC0402JR-070RL; Mistral Part No: 110011090036-R; Package: 0402; Part_type: RESISTORS\FIXED; Project: VP-4000-PROCESSOR; RoHS: RoHS; Temperature: -55°C+155°C; Tolerance: 5%; Voltage: NA; Wattage: 1/16W; Weight: 0.65mg; Datasheet: Y:\MIS_DATABASE\DATASHEETS\RESISTORS\RCXXXXL-SER_MAR18.PDF
R235 = RESISTOR: RES 2.2K 1/16W 5% 0402; Chkd/date: VASANTHA/061216; Crtd /date: BAVISH/021210; Custom_Duty: 15%; Customs_HS_Code: 85332119; Distributor_name: DIGIKEY; Distributor_part_number: 311-2.2KJRCT-ND; Footprint Path: Y:\MIS_DATABASE\Library\ALTIUM_TOOL\PCB_FOOTPRINTS\Altium_Footprint_Lib.PcbLib; Height: 0.40MM; Library Path: Y:\MIS_DATABASE\Library\ALTIUM_TOOL\SCHEMATICS_PARTS\MS_DISCRETE_Library.schlib; Mfr_name: YAGEO AMERICA; Mfr_part_number: RC0402JR-072K2L; Mistral Part No: 110010120018-R; Package: 0402; Part_type: RESISTORS\FIXED; Project: TE4; RoHS: RoHS; Temperature: -55°C+155°C; Tolerance: 5%; Voltage: NA; Wattage: 1/16W; Weight: 0.65mg; Datasheet: Y:\MIS_DATABASE\DATASHEETS\RESISTORS\RCXXXXL-SER_MAR18.PDF
R249 = RESISTOR: RES 51E 1/10W 5% 0402; Chkd/date: VASANTHA/291216; Crtd /date: MAZHAR/120505; Custom_Duty: 15%; Customs_HS_Code: 85332119; Distributor_name: DIGIKEY; Distributor_part_number: P51JCT-ND; Footprint Path: Y:\MIS_DATABASE\Library\ALTIUM_TOOL\PCB_FOOTPRINTS\Altium_Footprint_Lib.PcbLib; Height: 0.40MM; Library Path: Y:\MIS_DATABASE\Library\ALTIUM_TOOL\SCHEMATICS_PARTS\MS_DISCRETE_Library.schlib; Mfr_name: PANASONIC-ECG; Mfr_part_number: ERJ-2GEJ510X; Mistral Part No: 110009030962-R; Package: 0402; Part_type: RESISTORS\FIXED; Project: CTP02_REVA_BASE; RoHS: RoHS; Temperature: -55°C+155°C; Tolerance: 5%; Voltage: NA; Wattage: 1/10W; Weight: 0.8mg; Datasheet: Y:\MIS_DATABASE\DATASHEETS\RESISTORS\PAN-ERJSER_NOV17.PDF
R256 = RESISTOR: RES 4.87K 1/10W 1% 0402; Chkd/date: MAZHAR/150709; Crtd /date: USMAN/150109; Custom_Duty: 15%; Customs_HS_Code: 85332119; Distributor_name: DIGIKEY; Distributor_part_number: P4.87KLCT-ND; Footprint Path: Y:\MIS_DATABASE\Library\ALTIUM_TOOL\PCB_FOOTPRINTS\Altium_Footprint_Lib.PcbLib; Height: 0.40MM; Library Path: Y:\MIS_DATABASE\Library\ALTIUM_TOOL\SCHEMATICS_PARTS\MS_DISCRETE_Library.schlib; Mfr_name: PANASONIC-ECG; Mfr_part_number: ERJ-2RKF4871X; Mistral Part No: 110009030803-R; Package: 0402; Part_type: RESISTORS\FIXED; Project: BSN-II; RoHS: RoHS; Temperature: -55°C+155°C; Tolerance: 1%; Voltage: NA; Wattage: 1/10W; Weight: 0.8mg; Datasheet: Y:\MIS_DATABASE\DATASHEETS\RESISTORS\PAN-ERJSER_NOV17.PDF
R592 = RESISTOR: RES 100K 1/16W 1% 0402; Chkd/date: MANIRAJA/110917; Crtd /date: MANIRAJA/110917; Custom_Duty: 15%; Customs_HS_Code: 85332119; Distributor_name: DIGIKEY; Distributor_part_number: 311-100KLRCT-ND; Footprint Path: Y:\MIS_DATABASE\Library\ALTIUM_TOOL\PCB_FOOTPRINTS\Altium_Footprint_Lib.PcbLib; Height: 0.40MM; Library Path: Y:\MIS_DATABASE\Library\ALTIUM_TOOL\SCHEMATICS_PARTS\MS_DISCRETE_Library.schlib; Mfr_name: YAGEO AMERICA; Mfr_part_number: RC0402FR-07100KL; Mistral Part No: 110014060043-R; Package: 0402; Part_type: RESISTORS\FIXED; Project: CRADE RF CARD; RoHS: RoHS; Temperature: -55°C+155°C; Tolerance: 1%; Voltage: NA; Wattage: 1/16W; Weight: 0.65mg; Datasheet: Y:\MIS_DATABASE\DATASHEETS\RESISTORS\RCXXXXL-SER_MAR18.PDF
TP15-TP18 TP26 TP52 = TESTPOINT: TESTPOINT CIR 20 SMD; Chkd/date: SHREESHAIL/171006; Crtd /date: MAZHAR/171006; Custom_Duty: NA; Customs_HS_Code: NA; Distributor_name: NA; Distributor_part_number: NA; Footprint Path: Y:\MIS_DATABASE\Library\ALTIUM_TOOL\PCB_FOOTPRINTS\Altium_Footprint_Lib.PcbLib; Height: NA; Library Path: Y:\MIS_DATABASE\Library\ALTIUM_TOOL\SCHEMATICS_PARTS\MS_DISCRETE_Library.schlib; MECHANICAL 3D STEP FILE: NA; Mfr_name: LOCAL; Mistral Part No: NA; Package: SMD; Project: BT MODULE_CSRBC04; RoHS: NA; Temperature: NA; Tolerance: NA; Voltage: NA; Wattage: NA; Weight: NA; Datasheet: NA
TP27 TP35 = TESTPOINT: TESTPOINT CIR 40 SMD; Chkd/date: MAZHAR/190505; Crtd /date: MAZHAR/190505; Distributor_name: NA; Distributor_part_number: NA; Footprint Path: Y:\MIS_DATABASE\Library\ALTIUM_TOOL\PCB_FOOTPRINTS\Altium_Footprint_Lib.PcbLib; Height: NA; Library Path: Y:\MIS_DATABASE\Library\ALTIUM_TOOL\SCHEMATICS_PARTS\MS_DISCRETE_Library.schlib; MECHANICAL 3D STEP FILE: NA; Mfr_name: LOCAL; Mistral Part No: 130009030933; Package: SMD; Project: RAINIER-3; RoHS: NA; Temperature: NA; Tolerance: NA; Voltage: NA; Wattage: NA; Weight: NA; Datasheet: NA
U24 = TPD4E02B04DQAR_USON10: DIODE 4-CHANNEL ESD PROTECTION FOR USB-C USON10; Chkd/date: VASANTHA/220217; Crtd /date: MANIRAJA/210217; Custom_Duty: 15%; Customs_HS_Code: 85412900; Distributor_name: DIGIKEY; Distributor_part_number: 296-43875-1-ND; Footprint Path: Y:\MIS_DATABASE\Library\ALTIUM_TOOL\PCB_FOOTPRINTS\Altium_Footprint_Lib.PcbLib; Height: 0.55MM; Library Path: Y:\MIS_DATABASE\Library\ALTIUM_TOOL\SCHEMATICS_PARTS\MS_DISCRETE_Library.schlib; Mfr_name: TEXAS INSTRUMENTS; Mistral Part No: 130017020038-R; Package: USON10; Part_type: DIODE\TVS; Project: SD820_NANO_SOM; RoHS: RoHS; Temperature: -40°C+125°C; Tolerance: NA; Voltage: NA; Wattage: NA; Weight: 28mg; Datasheet: Y:\MIS_DATABASE\DATASHEETS\DISCRETES\DIODES\TPD4E02B04DQAR.PDF
U36 = LM4040B25IDCKR_SC70-5: IC PRECISION MICROPOWER SHUNT VOLTAGE REFERENCE SC70-5; Chkd/date: MANIRAJA/230817; Crtd /date: MANIRAJA/230817; Custom_Duty: 15%; Customs_HS_Code: 85423100; Distributor_name: DIGIKEY; Distributor_part_number: 296-20873-1-ND; Height: 1.10MM; Mfr_name: TEXAS INSTRUMENTS; Mistral Part No: 142017080015-R; Package: SC70-5; Part_type: ICS\POWER\VOLTAGE REGULATOR; Project: TI_MAXIE_CPB; RoHS: RoHS; Temperature: -40°C+85°C; Tolerance: NA; Voltage: NA; Wattage: NA; Weight: 30mg; Datasheet: Y:\MIS_DATABASE\DATASHEETS\ICS\POWER\LM4040B25I.PDF
U37 = TM4C1294NCPDTT3R_TQFP128: IC 32-BIT MICROCONTROLLER WITH 1MB FLASH TQFP128; Chkd/date: MANIRAJA/220817; Crtd /date: MANIRAJA/220817; Custom_Duty: 15%; Customs_HS_Code: 85423100; Distributor_name: DIGIKEY; Distributor_part_number: TM4C1294NCPDTT3R-ND; Height: 1.20MM; Mfr_name: TEXAS INSTRUMENTS; Mistral Part No: 141217080002-R; Package: TQF9128; Part_type: ICS\DIGITAL\MICROCONTROLLER; Project: TI_MAXIE_CPB; RoHS: RoHS; Temperature: -40°C+105°C; Tolerance: NA; Voltage: NA; Wattage: NA; Weight: 503.5mg; Datasheet: Y:\MIS_DATABASE\DATASHEETS\ICS\DIGITAL\MICROCONTROLLER\TM4C1294NCPD.PDF
U38 = TPS74618_WSON6: IC 1A 3.3V OUTPUT LDO REGULATOR WITH POWER-GOOD WSON6; Chkd/date: ALVY/081220; Crtd /date: MANIRAJA/081220; Custom_Duty: 15%; Customs_HS_Code: 85423100; Distributor_name: DIGIKEY; Distributor_part_number: 296-TPS74633PQWDRVRQ1CT-ND; Footprint Path: Y:\MIS_DATABASE\Library\ALTIUM_TOOL\PCB_FOOTPRINTS\Altium_Footprint_Lib.PcbLib; Height: 0.80MM; Library Path: Y:\MIS_DATABASE\Library\ALTIUM_TOOL\SCHEMATICS_PARTS\MS_MISCPOWER_Library.schlib; Mfr_name: TEXAS INSTRUMENTS; Mistral Part No: 142020120011-R; Package: WSON6; Part_type: ICS\POWER\VOLTAGE REGULATOR; Project: TI_AM243x LP EVM; RoHS: RoHS; Temperature: -40°C+125°C; Tolerance: NA; Voltage: NA; Wattage: NA; Weight: NA; Datasheet: Y:\MIS_DATABASE\DATASHEETS\ICS\POWER\TPS74618-Q1.PDF
U45 = SN74AVC4T245PW_TSSOP16: IC 4-BIT DUAL SUPPLY BUS TRANSCEIVER TSSOP16; Chkd/date: SHREESHAIL/030506; Crtd /date: MAZHAR/270406; Custom_Duty: 15%; Customs_HS_Code: 85423100; Distributor_name: MOUSER; Distributor_part_number: 595-SN74AVC4T245PW; Height: 1.20MM; Mfr_name: TEXAS INSTRUMENTS; Mistral Part No: 141009030111-R; Package: TSSOP16; Part_type: ICS\DIGITAL\COMBINATIONAL; Project: VOCERA; RoHS: Sb/ Br FREE; Datasheet: Y:\MIS_DATABASE\DATASHEETS\ICS\DIGITAL\BUSTRANSCEIVER\SN74AVC4T245.PDF
Y1 = CRY4_13: CRY 16.000MHz 18pF SMD; Chkd/date: ALVY/081220; Crtd /date: MANIRAJA/081220; Custom_Duty: 24%; Customs_HS_Code: 85439000; Distributor_name: NA; Distributor_part_number: NA; Footprint Path: Y:\MIS_DATABASE\Library\ALTIUM_TOOL\PCB_FOOTPRINTS\Altium_Footprint_Lib.PcbLib; Height: 0.80MM; Library Path: Y:\MIS_DATABASE\Library\ALTIUM_TOOL\SCHEMATICS_PARTS\MS_DISCRETE_Library.schlib; Mfr_name: WURTH ELEKTRONIK; Mfr_part_number: 830055951; Mistral Part No: 130020120020-R; Package: SMD; Part_type: CRYSTAL; Project: TI_AM243x LP EVM; RoHS: RoHS; Temperature: -40°C+85°C; Tolerance: NA; Voltage: NA; Wattage: NA; Weight: NA; Datasheet: Y:\MIS_DATABASE\DATASHEETS\MISC\CRY_OSC\830055951.PDF
C112 = CAP: CAP CERAMIC 0.1uF 16V 10% X5R 0201; Alt_Mfr_name: YAGEO AMERICA; Alt_Mfr_part_number: CC0402KRX5R8BB104; Chkd/date: MANIRAJA/230118; Crtd /date: MANIRAJA/230118; Custom_Duty: 15%; Customs_HS_Code: 85322990; Distributor_name: DIGIKEY; Distributor_part_number: 490-14305-1-ND; Footprint Path: Y:\MIS_DATABASE\Library\ALTIUM_TOOL\PCB_FOOTPRINTS\Altium_Footprint_Lib.PcbLib; Height: 0.33MM; Library Path: Y:\MIS_DATABASE\Library\ALTIUM_TOOL\SCHEMATICS_PARTS\MS_DISCRETE_Library.schlib; Mfr_name: MURATA; Mfr_part_number: GRM033R61C104KE14D; Mistral Part No: 120009030072-R; Package: 0201; Part_type: CAPACITORS\CERAMIC; Project: TI_MAXIE_CPB; RoHS: RoHS; Temperature: -55°C+85°C; Tolerance: 10%; Voltage: 16V; Wattage: NA; Weight: 0.33mg; Datasheet: Y:\MIS_DATABASE\DATASHEETS\CAPACITORS\GRM033R61C104KE14.PDF
LD1 LD12-LD15 = DIODE_LED: DIODE LED BRIGHT GREEN SMD; Chkd/date: MANIRAJA/261120; Crtd /date: ALVY/261120; Custom_Duty: 24%; Customs_HS_Code: 85439000; Distributor_name: DIGIKEY; Distributor_part_number: 732-13425-1-ND; Footprint Path: Y:\MIS_DATABASE\Library\ALTIUM_TOOL\PCB_FOOTPRINTS\Altium_Footprint_Lib.PcbLib; Height: 0.35MM; Library Path: Y:\MIS_DATABASE\Library\ALTIUM_TOOL\SCHEMATICS_PARTS\MS_OPTO_Library.schlib; Mfr_name: WURTH ELECTRONIK; Mistral Part No: 130020110071-R; Package: SMD; Part_type: OPTO\LED; Project: AM64X_SKEVM; RoHS: RoHS; Temperature: -40°C+85°C; Tolerance: NA; Voltage: NA; Wattage: NA; Weight: 29.3mg; Datasheet: Y:\MIS_DATABASE\DATASHEETS\DISCRETES\LEDS\150040VS73220.PDF
LD2 = DIODE_LED: DIODE LED RED SMD; Chkd/date: MANIRAJA/100920; Crtd /date: ALVY/100920; Custom_Duty: 24%; Customs_HS_Code: 85439000; Distributor_name: DIGIKEY; Distributor_part_number: 732-13422-1-ND; Footprint Path: Y:\MIS_DATABASE\Library\ALTIUM_TOOL\PCB_FOOTPRINTS\Altium_Footprint_Lib.PcbLib; Height: 0.35MM; Library Path: Y:\MIS_DATABASE\Library\ALTIUM_TOOL\SCHEMATICS_PARTS\MS_OPTO_Library.schlib; Mfr_name: WURTH ELECTRONICS; Mistral Part No: 130020090020-R; Package: SMD; Part_type: OPTO\LED; Project: AM64X_SKEVM; RoHS: RoHS; Temperature: -40°C+85°C; Tolerance: NA; Voltage: NA; Wattage: NA; Weight: 29.3mg; Datasheet: Y:\MIS_DATABASE\DATASHEETS\DISCRETES\LEDS\150040RS73220.PDF
LD3 = LED4_150066RV54050: DIODE LED RED/GREEN SMD; Chkd/date: MANIRAJA/031220; Crtd /date: ALVY/031220; Custom_Duty: 24%; Customs_HS_Code: 85439000; Distributor_name: DIGIKEY; Distributor_part_number: 732-150066RV54050CT-ND; Footprint Path: Y:\MIS_DATABASE\Library\ALTIUM_TOOL\PCB_FOOTPRINTS\Altium_Footprint_Lib.PcbLib; Height: 0.65MM; Library Path: Y:\MIS_DATABASE\Library\ALTIUM_TOOL\SCHEMATICS_PARTS\MS_OPTO_Library.schlib; Mfr_name: WURTH ELECTRONICS; Mistral Part No: 130020120014-R; Package: SMD; Part_type: OPTO\LED; Project: TI_AM243x LP EVM; RoHS: RoHS; Temperature: -40°C+85°C; Tolerance: NA; Voltage: NA; Wattage: NA; Weight: NA; Datasheet: Y:\MIS_DATABASE\DATASHEETS\DISCRETES\LEDS\150066RV54050.PDF
Q4-Q6 Q9 = MOSFET_CSD17313Q2: IC MOSFET N-CHANNEL NEXFET 25V WSON6; Chkd/date: ALVY/071220; Crtd /date: MANIRAJA/071220; Custom_Duty: 15%; Customs_HS_Code: 85423100; Distributor_name: DIGIKEY; Distributor_part_number: 296-25260-1-ND; Footprint Path: Y:\MIS_DATABASE\Library\ALTIUM_TOOL\PCB_FOOTPRINTS\Altium_Footprint_Lib.PcbLib; Height: 0.80MM; Library Path: Y:\MIS_DATABASE\Library\ALTIUM_TOOL\SCHEMATICS_PARTS\MS_MOSFET_Library.schlib; Mfr_name: TEXAS INSTRUMENTS; Mistral Part No: 142020120008-R; Package: WSON6; Part_type: ICS\POWER\MOSFET; Project: TI_AM243x LP EVM; RoHS: RoHS; Temperature: -55°C+150°C; Tolerance: NA; Voltage: NA; Wattage: NA; Weight: 8.7mg; Datasheet: Y:\MIS_DATABASE\DATASHEETS\ICS\POWER\CSD16301Q2.PDF
R169 = RESISTOR: RES 110E 1/10W 5% 0402; Chkd/date: SHREESHAIL/121205; Crtd /date: MAZHAR/120505; Custom_Duty: 15%; Customs_HS_Code: 85332119; Distributor_name: DIGIKEY; Distributor_part_number: P110JCT-ND; Footprint Path: Y:\MIS_DATABASE\Library\ALTIUM_TOOL\PCB_FOOTPRINTS\Altium_Footprint_Lib.PcbLib; Height: 0.40MM; Library Path: Y:\MIS_DATABASE\Library\ALTIUM_TOOL\SCHEMATICS_PARTS\MS_DISCRETE_Library.schlib; Mfr_name: PANASONIC-ECG; Mfr_part_number: ERJ-2GEJ111X; Mistral Part No: 110009030230-R; Package: 0402; Part_type: RESISTORS\FIXED; Project: HSE; RoHS: RoHS; Temperature: -55°C+155°C; Tolerance: 5%; Voltage: NA; Wattage: 1/10W; Weight: 0.8mg; Datasheet: Y:\MIS_DATABASE\DATASHEETS\RESISTORS\PAN-ERJSER_NOV17.PDF
U35 = TPIC2810D_SOIC16: IC 8-BIT LED DRIVER WITH I2C INTERFACE SOIC16; Chkd/date: MANIRAJA/230817; Crtd /date: MANIRAJA/220817; Custom_Duty: 15%; Customs_HS_Code: 85423100; Distributor_name: DIGIKEY; Distributor_part_number: 296-13746-5-ND; Height: 1.75MM; Mfr_name: TEXAS INSTRUMENTS; Mistral Part No: 141017080026-R; Package: SOIC16; Part_type: ICS\INTERFACE; Project: TI_MAXIE_CPB; RoHS: RoHS; Temperature: -40°C+125°C; Tolerance: NA; Voltage: NA; Wattage: NA; Weight: NA; Datasheet: Y:\MIS_DATABASE\DATASHEETS\ICS\INTERFACE\TPIC2810D.PDF
C136 = CAP: CAP CERAMIC 10uF 10V 20% X5R 0402; Chkd/date: MANIRAJA/300520; Crtd /date: ALVY/260520; Custom_Duty: 15%; Customs_HS_Code: 85322990; Distributor_name: DIGIKEY; Distributor_part_number: 490-GRM155R61A106ME11DTR-ND; Footprint Path: Y:\MIS_DATABASE\Library\ALTIUM_TOOL\PCB_FOOTPRINTS\Altium_Footprint_Lib.PcbLib; Height: 0.55MM; Library Path: Y:\MIS_DATABASE\Library\ALTIUM_TOOL\SCHEMATICS_PARTS\MS_DISCRETE_Library.schlib; Mfr_name: MURATA; Mfr_part_number: GRM155R61A106ME11D; Mistral Part No: 120013110019-R; Package: 0402; Part_type: CAPACITORS\CERAMIC; Project: QCS610_NANOSOM; RoHS: RoHS; Temperature: -55°C+85°C; Tolerance: 20%; Voltage: 10V; Wattage: NA; Weight: 3.1mg; Datasheet: Y:\MIS_DATABASE\DATASHEETS\CAPACITORS\MURATA-GXX-SER_NOV17.PDF
C143 = CAP: CAP CERAMIC 3.3uF 10V 20% X5R AUTO 0603; Chkd/date: MANIRAJA/210817; Crtd /date: MANIRAJA/210817; Custom_Duty: 15%; Customs_HS_Code: 85322990; Distributor_name: DIGIKEY; Distributor_part_number: 445-12446-1-ND; Footprint Path: Y:\MIS_DATABASE\Library\ALTIUM_TOOL\PCB_FOOTPRINTS\Altium_Footprint_Lib.PcbLib; Height: 0.90MM; Library Path: Y:\MIS_DATABASE\Library\ALTIUM_TOOL\SCHEMATICS_PARTS\MS_DISCRETE_Library.schlib; Mfr_name: TDK CORPORATION; Mfr_part_number: CGA3E1X5R1A335M080AC; Mistral Part No: 120017080015-R; Package: 0603; Part_type: CAPACITORS\CERAMIC; Project: TI_RF_DC CARD; RoHS: RoHS; Temperature: -55°C+85°C; Tolerance: 20%; Voltage: 10V; Wattage: NA; Weight: 2mg; Datasheet: Y:\MIS_DATABASE\DATASHEETS\CAPACITORS\CGA3E1X5R1A335M080AC.PDF
C171 C255 = CAP: CAP CERAMIC 4.7uF 10V 20% X5R 0402; Chkd/date: MANIRAJA/110718; Crtd /date: ALVY/110718; Custom_Duty: 15%; Customs_HS_Code: 85322990; Distributor_name: DIGIKEY; Distributor_part_number: 490-14306-1-ND; Footprint Path: Y:\MIS_DATABASE\Library\ALTIUM_TOOL\PCB_FOOTPRINTS\Altium_Footprint_Lib.PcbLib; Height: 0.65MM; Library Path: Y:\MIS_DATABASE\Library\ALTIUM_TOOL\SCHEMATICS_PARTS\MS_DISCRETE_Library.schlib; Mfr_name: MURATA; Mfr_part_number: GRM155R61A475MEAAD; Mistral Part No: 120012060002-R; Package: 0402; Part_type: CAPACITORS\CERAMIC; Project: TI_J7SVB_PCIE_ADD-ON-CARD; RoHS: RoHS; Temperature: -55°C+85°C; Tolerance: 20%; Voltage: 10V; Wattage: NA; Weight: 14mg; Datasheet: Y:\MIS_DATABASE\DATASHEETS\CAPACITORS\GRM155R61A475MEAAD.PDF

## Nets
DGND: C102.2 C104.2 C105.2 C112.1 C114.2 C120.1 C121.2 C128.2 C129.2 C131.1 C132.2 C133.2 C134.2 C136.2 C137.2 C138.2 C139.2 C140.2 C141.2 C143.2 C145.2 C149.2 C150.2 C151.2 C154.2 C158.2 C160.2 C163.2 C165.2 C167.2 C168.2 C169.2 C170.2 C171.2 C172.2 C173.2 C175.2 C180.2 C181.2 C182.2 C186.2 C187.2 C188.2 C191.2 C192.2 C196.2 C199.2 C200.2 C201.2 C202.2 C203.2 C205.2 C208.2 C211.2 C212.2 C213.2 C214.2 C215.2 C223.2 C227.2 C233.2 C234.2 C235.2 C237.2 C239.2 C240.2 C242.2 C244.2 C245.2 C246.2 C247.2 C249.2 C250.2 C251.2 C253.2 C254.2 C255.2 C262.2 C263.2 C268.2 J20.5(GND) LD10.1(CATHODE) LD11.1(CATHODE) Q4.4(S1) Q4.7(S2) Q5.4(S1) Q5.7(S2) Q6.4(S1) Q6.7(S2) Q9.4(S1) Q9.7(S2) R159.2 R165.1 R172.1 R173.1 R174.1 R212.2 R241.1 R243.1 R245.1 R256.2 R592.2 U18.A1(VSS) U18.A2(VSS) U18.A20(VSS) U18.A21(VSS) U18.AA1(VSS) U18.AA2(VSS) U18.AA20(VSS) U18.AA21(VSS) U18.B1(VSS) U18.B21(VSS) U18.D10(VSS) U18.D16(VSS) U18.D17(VSS) U18.E6(VSS) U18.E11(VSS) U18.E13(VSS) U18.F8(VSS) U18.F17(VSS) U18.G16(VSS) U18.H6(VSS) U18.H7(VSS) U18.H16(VSS) U18.J5(VSS) U18.J6(VSS) U18.J11(VSS) U18.J16(VSS) U18.K6(VSS) U18.K7(VSS) U18.K8(VSS) U18.K16(VSS) U18.L10(VSS) U18.L11(VSS) U18.L12(VSS) U18.M7(VSS) U18.M15(VSS) U18.M16(VSS) U18.N6(VSS) U18.N11(VSS) U18.N13(VSS) U18.P7(VSS) U18.P11(VSS) U18.P15(VSS) U18.P16(VSS) U18.R6(VSS) U18.R11(VSS) U18.T14(VSS) U18.U6(VSS) U18.Y1(VSS) U18.Y21(VSS) U24.3(GND) U24.8(GND) U35.8(~{G}) U35.16(GND) U36.1(ANODE) U37.10(GNDA) U37.17(GND) U37.48(GND) U37.55(GND) U37.58(GND) U37.64(~{WAKE}) U37.66(XOSC0) U37.80(GND) U37.114(GND) U38.3(GND) U38.7(EP) U45.3(2DIR) U45.5(1A2) U45.7(2A2) U45.8(GND1) U45.9(GND2) U45.10(2B2) U45.12(1B2) U45.14(~{2OE}) U45.15(~{1OE}) Y1.2 Y1.4 ; also on sheet 10 11 12 13 14 15 16 17 18 19 20 21 25 26 27 28
VBAT_XDS: C208.1 R249.2 U37.68(VBAT)
VBUS_XDS_USB: C170.1 J20.1(VBUS) R219.1 R222.2 TP27.1(TP) U24.1(IO1) U24.10(NC4) U38.4(EN) U38.6(IN)
VCC3V3_XDS: C104.1 C121.1 C151.1 C154.1 C180.1 C181.1 C182.1 C191.1 C240.1 C242.1 C262.1 R98.2 R99.2 R100.2 R101.2 R108.2 R109.2 R235.1 R246.1 R249.1 TP35.1(TP) U37.7(VDD) U37.8(VDDA) U37.16(VDD) U37.26(VDD) U37.28(VDD) U37.39(VDD) U37.47(VDD) U37.51(VDD) U37.52(VDD) U37.69(VDD) U37.79(VDD) U37.90(VDD) U37.101(VDD) U37.113(VDD) U37.122(VDD) U38.1(OUT) U45.16(VCCB) ; also on sheet 12
VDD_CORE_0V85: C136.1 C137.1 C138.1 C139.1 C163.1 C165.1 C186.1 C187.1 C188.1 C199.1 C200.1 C201.1 C211.1 C212.1 C214.1 C227.1 C234.1 C239.1 C244.1 C247.1 C250.1 C251.1 C254.1 C255.1 U18.F11(VDD_CORE) U18.G5(VDDR_CORE) U18.G6(VDDR_CORE) U18.G10(VDD_CORE) U18.H8(VDD_CORE) U18.H15(VDD_CORE) U18.J9(VDD_CORE) U18.J10(VDDR_CORE) U18.J12(VDDR_CORE) U18.K11(VDD_CORE) U18.K14(VDD_CORE) U18.L9(VDD_CORE) U18.L13(VDD_CORE) U18.M8(VDD_CORE) U18.M14(VDD_CORE) U18.N9(VDD_CORE) U18.N10(VDD_CORE) U18.P8(VDDR_CORE) U18.P14(VDDR_CORE) U18.R9(VDD_CORE) U18.R10(VDDR_CORE) U18.R12(VDD_CORE) U18.R13(VDD_CORE) ; also on sheet 10 25 27
VDDC_1V2_XDS: C102.1 C105.1 C132.1 U37.87(VDDC) U37.115(VDDC)
VDDSHV_3V3: C133.1 C134.1 C140.1 C141.1 C145.1 C158.1 C167.1 C168.1 C169.1 C171.1 C175.1 C202.1 C203.1 C205.1 C213.1 C215.1 C235.1 C237.1 C245.1 C246.1 C249.1 C253.1 R261.2 TP52.1(TP) U18.C13(VDDSHV0) U18.D13(VDDSHV0) U18.E7(VDDSHV_MCU) U18.E8(VDDSHV_MCU) U18.E9(VDDSHV_MCU) U18.E14(VDDSHV0) U18.L6(VDDSHV1) U18.M6(VDDSHV1) U18.N16(VDDSHV4) U18.N17(VDDSHV4) U18.P5(VDDSHV1) U18.P6(VDDSHV1) U18.R17(VDDSHV3) U18.T8(VDDSHV2) U18.T11(VDDSHV2) U18.T17(VDDSHV3) U18.U7(VDDSHV2) U18.U8(VDDSHV2) U18.U11(VDDSHV2) ; also on sheet 25
VDDSHV_SDIO: C143.1 C160.1 C172.1 U18.J17(CAP_VDDSHV_MMC1) U18.L16(VDDSHV5) U18.L17(VDDSHV5) ; also on sheet 19
CAP_VDDS0: C192.1 U18.D12(CAP_VDDS0)
CAP_VDDS1: C233.1 U18.N5(CAP_VDDS1)
CAP_VDDS2: C196.1 U18.U9(CAP_VDDS2)
CAP_VDDS3: C173.1 U18.R16(CAP_VDDS3)
CAP_VDDS4: C149.1 U18.N18(CAP_VDDS4)
CAP_VDDS5: C150.1 U18.M18(CAP_VDDS5)
CAP_VDDS_MCU: C223.1 U18.D9(CAP_VDDS_MCU)
LED1: LD15.1(CATHODE) U35.3(DRAIN0)
LED2: LD14.1(CATHODE) U35.4(DRAIN1)
LED3: LD13.1(CATHODE) U35.5(DRAIN2)
LED4: LD12.1(CATHODE) U35.6(DRAIN3)
LED_DRV_A0: R245.2 U35.9(A0)
LED_DRV_A1: R241.2 U35.10(A1)
LED_DRV_A2: R243.2 U35.7(A2)
MAIN_UART0_RXD: U45.6(2A1) ; also on sheet 11
MAIN_UART0_TXD: R592.1 U45.4(1A1) ; also on sheet 11
OSC0: C131.2 U37.88(OSC0) Y1.3
OSC1: C120.2 U37.89(OSC1) Y1.1
SoC_I2C0_SCL: U35.15(SCL) ; also on sheet 11 15 19
SoC_I2C0_SDA: U35.2(SDA) ; also on sheet 11 15 19
TEST_LED1_GREEN: Q6.3(G) R173.2 ; also on sheet 11
TEST_LED2_RED: Q5.3(G) R172.2 ; also on sheet 11
TEST_LED3_RED: Q9.3(G) R174.2 ; also on sheet 11
TEST_LED4_GREEN: Q4.3(G) R165.2 ; also on sheet 11
TM4C129_TCK: TP18.1(TP) U37.100(PC0/TCK/SWCLK)
TM4C129_TDI: TP16.1(TP) U37.98(PC2/TDI)
TM4C129_TDO: TP15.1(TP) U37.97(PC3/TDO/SWO)
TM4C129_TMS: TP17.1(TP) U37.99(PC1/TMS/SWDIO)
VPP_1V8: U18.E16(VPP) ; also on sheet 28
VSYS_3V3: C112.2 C268.1 R166.1 R167.1 R168.1 R169.1 R261.1 R282.1 R283.1 R284.1 R285.1 U35.1(VCC) U45.1(VCCA) U45.2(1DIR) ; also on sheet 10 11 12 13 14 15 16 17 18 19 20 21 25 27 28
XDS110_DEBUG_ID4: R98.1 U37.63(PK4)
XDS110_DEBUG_ID5: R99.1 U37.62(PK5)
XDS110_DEBUG_ID6: R100.1 U37.61(PK6)
XDS110_DEBUG_ID7: R101.1 U37.60(PK7)
XDS110_EMU0: R109.1 U37.42(PF0) ; also on sheet 12
XDS110_EMU1: R108.1 U37.43(PF1) ; also on sheet 12
XDS110_PROG_STAZ1: R114.2 U37.4(PD3/AIN12)
XDS110_PROG_STAZ2: R111.2 U37.3(PD2/AIN13)
XDS110_TCK: U37.35(PA2/SSI0CLK) ; also on sheet 12
XDS110_TDI: U37.38(PA5/SSI0XDAT1) ; also on sheet 12
XDS110_TDO: U37.37(PA4/SSI0XDAT0) ; also on sheet 12
XDS110_TMS: U37.36(PA3/SSI0FSS) ; also on sheet 12
XDS110_TRST#: U37.40(PA6) ; also on sheet 12
XDS110_UART1_RXD: U37.33(PA0/U0RX) U45.13(1B1)
XDS110_UART1_TXD: U37.34(PA1/U0TX) U45.11(2B1)
XDS110_VBUS_DET: R212.1 R219.2 U37.1(PD0/AIN15)
XDS_RBIAS: R256.1 U37.59(RBAIS)
XDS_RESET#: R246.2 TP26.1(TP) U37.70(~{RST})
XDS_SHIELD: C263.1 J20.6(SH1) J20.7(SH2) J20.8(SH3) J20.9(SH4) R159.1
XDS_USB_D_N: J20.2(D-) U24.4(IO3) U24.7(NC2) U37.93(PL7/USB0DM)
XDS_USB_D_P: J20.3(D+) U24.5(IO4) U24.6(NC1) U37.94(PL6/USB0DP)
XDS_USB_ID: J20.4(ID) R231.2 U24.2(IO2) U24.9(NC3)
XDS_VREF: C128.1 C129.1 R235.2 U36.3(CATHODE) U37.9(VREFA+)
N17247526: LD15.2(ANODE) R282.2
N17247539: LD14.2(ANODE) R283.2
N17247599: LD13.2(ANODE) R284.2
N17247637: LD12.2(ANODE) R285.2
N30212600: LD2.1(CATHODE) Q5.1(D1) Q5.2(D2) Q5.5(D3) Q5.6(D4) Q5.8(D5)
N30212640: LD1.2(ANODE) R167.2
N30212699: LD1.1(CATHODE) Q6.1(D1) Q6.2(D2) Q6.5(D3) Q6.6(D4) Q6.8(D5)
N30213674: LD2.2(ANODE) R166.2
N30217069: C114.1 R222.1 U37.96(PB1/USB0VBUS)
N30217074: R231.1 U37.95(PB0/USB0ID)
N30217111: LD10.2(ANODE) R111.1
N30217160: LD11.2(ANODE) R114.1
N30693218: LD3.3(A2) R168.2
N30693408: LD3.2(A1) R169.2
N30811240: LD3.4(C2) Q9.1(D1) Q9.2(D2) Q9.5(D3) Q9.6(D4) Q9.8(D5)
N30811389: LD3.1(C1) Q4.1(D1) Q4.2(D2) Q4.5(D3) Q4.6(D4) Q4.8(D5)

Not connected (* = marked no-connect by the designer): U35 11(DRAIN4)* 12(DRAIN5)* 13(DRAIN6)* 14(DRAIN7)*; U36 2(NC1)* 4(NC2)* 5(NC3)*; U37 2(PD1/AIN14)* 5(PQ0)* 6(PQ1)* 11(PQ2)* 12(PE3/AIN0)* 13(PE2/AIN1)* 14(PE1/AIN2)* 15(PE0/AIN3)* 18(PK0/AIN16)* 19(PK1/AIN17)* 20(PK2/AIN18)* 21(PK3/AIN19)* 22(PC7/C0-)* 23(PC6/C0+)* 24(PC5/C1+)* 25(PC4/C1-)* 27(PQ3)* 29(PH0)* 30(PH1)* 31(PH2)* 32(PH3)* 41(PA7)* 44(PF2)* 45(PF3)* 46(PF4)* 49(PG0)* 50(PG1)* 53(EN0RXIN)* 54(EN0RXIP)* 56(EN0RX0N)* 57(EN0RX0P)* 65(~{HIB})* 67(XOSC1)* 71(PM7)* 72(PM6)* 73(PM5)* 74(PM4)* 75(PM3)* 76(PM2)* 77(PM1)* 78(PM0)* 81(PL0)* 82(PL1)* 83(PL2)* 84(PL3)* 85(PL4)* 86(PL5)* 91(PB2/I2C0SCL)* 92(PB3/I2C0SDA)* 102(PQ4)* 103(PP2)* 104(PP3)* 105(PP4)* 106(PP5)* 107(PN0)* 108(PN1)* 109(PN2)* 110(PN3)* 111(PN4)* 112(PN5)* 116(PJ0)* 117(PJ1)* 118(PP0/C2+)* 119(PP1/C2-)* 120(PB5/AIN11)* 121(PB4/AIN10)* 123(PE4/AIN9)* 124(PE5/AIN8)* 125(PD4/AIN7)* 126(PD5/AIN6)* 127(PD6/AIN5)* 128(PD7/AIN4)*; U38 2(NC)* 5(PG)*

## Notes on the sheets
sheet 22
- XDS110 Debugger
- Silkscreen for J20:
  "XDS110, UART"
- GREEN
- RED
- 90E
- UART Buffer for XDS110
sheet 23
- Industrial Communication LEDs
- GREEN
- GREEN
- GREEN
- GREEN
- I2C ADDRESS SET TO 0x60
- RED
- GREEN
- (From SoC GPIO)
- (From SoC GPIO)
- (From SoC GPIO)
- (From SoC GPIO)
sheet 24
- SoC Digital POWER & DECAPs
- VDD_CORE_OV85 DECAPs
- Place one 0.1uF cap near each Pin
- VDDSHV_SDIO DECAPs
- VDDSHV_3V3 DECAPs
- Place one 0.1uF cap near each Pin
